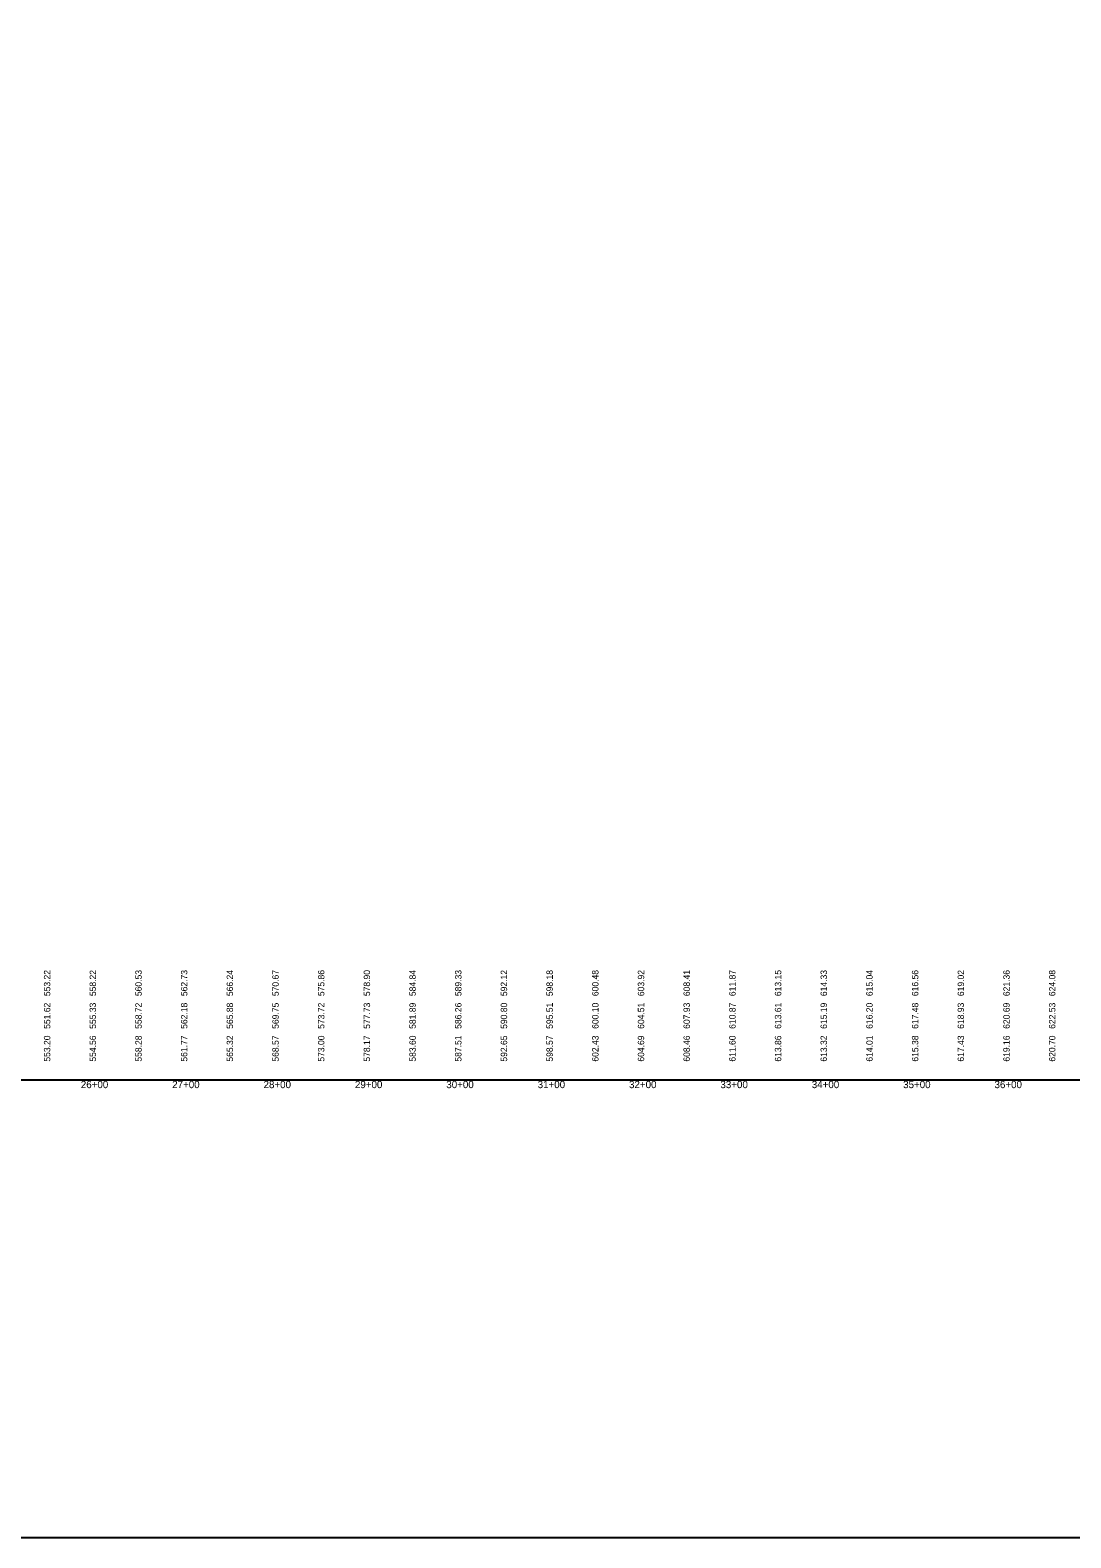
# Model space of a CAD drawing. Extents: x 1511486 to 1516886, y 901686 to 906985.
# Drawn here: x 1514602 to 1515741, y 903685 to 905335 of the extents above; entities that cross this region are included whole.
import ezdxf

# ---------------------------------------------------------------- set-up
doc = ezdxf.new("R2010")
doc.units = 0
for name, color, linetype in [('RD_DDB_StaTX', 7, 'Continuous'), ('RD_DDB_StripGrade', 7, 'Continuous'), ('RD_GPK_Profile_Cell', 7, 'Continuous'), ('RD_Sketch2', 7, 'Continuous'), ('RD_Sketch3', 7, 'Continuous')]:
    doc.layers.add(name, color=color, linetype=linetype)

msp = doc.modelspace()

# ---------------------------------------------------------------- linework, layer by layer
at = {"layer": 'RD_GPK_Profile_Cell'}
msp.add_line((1512074.7, 904186.4), (1516174.7, 904186.4), dxfattribs=at)
at = {"layer": 'RD_Sketch3'}
msp.add_lwpolyline([(1511486.2, 906985.3), (1516886.2, 906985.3), (1516886.2, 903685.3), (1511486.2, 903685.3)], close=True, dxfattribs=at)

# ---------------------------------------------------------------- texts
at = {"layer": 'RD_DDB_StaTX'}
for s, p in [('26+00', (1514657.1, 904177.4)), ('27+00', (1514757.1, 904177.4)), ('28+00', (1514857.1, 904177.4)), ('29+00', (1514957.1, 904177.4)), ('30+00', (1515057.1, 904177.4)), ('31+00', (1515157.1, 904177.4)), ('32+00', (1515257.1, 904177.4)), ('33+00', (1515357.1, 904177.4)), ('34+00', (1515457.1, 904177.4)), ('35+00', (1515557.1, 904177.4)), ('36+00', (1515657.1, 904177.4))]:
    msp.add_text(s, height=8, dxfattribs=at).set_placement(p)
at = {"layer": 'RD_DDB_StripGrade'}
for s, p in [('551.62', (1514623.7, 904242.3)), ('555.33', (1514673.7, 904242.3)), ('558.72', (1514723.7, 904242.3)), ('562.18', (1514773.7, 904242.3)), ('565.88', (1514823.7, 904242.3)), ('569.75', (1514873.7, 904242.3)), ('573.72', (1514923.7, 904242.3)), ('577.73', (1514973.7, 904242.3)), ('581.89', (1515023.7, 904242.3)), ('586.26', (1515073.7, 904242.3)), ('590.80', (1515123.7, 904242.3)), ('595.51', (1515173.7, 904242.3)), ('600.10', (1515223.7, 904242.3)), ('604.51', (1515273.7, 904242.3)), ('607.93', (1515323.7, 904242.3)), ('610.87', (1515373.7, 904242.3)), ('613.61', (1515423.7, 904242.3)), ('615.19', (1515473.7, 904242.3)), ('616.20', (1515523.7, 904242.3)), ('617.48', (1515573.7, 904242.3)), ('618.93', (1515623.7, 904242.3)), ('620.69', (1515673.7, 904242.3)), ('622.53', (1515723.7, 904242.3))]:
    msp.add_text(s, height=7, rotation=90, dxfattribs=at).set_placement(p)
at = {"layer": 'RD_Sketch2'}
for s, p in [('553.22', (1514623.7, 904278.1)), ('558.22', (1514673.7, 904278.1)), ('560.53', (1514723.7, 904278.1)), ('562.73', (1514773.7, 904278.1)), ('566.24', (1514823.7, 904278.1)), ('570.67', (1514873.7, 904278.1)), ('575.86', (1514923.7, 904278.1)), ('578.90', (1514973.7, 904278.1)), ('584.84', (1515023.7, 904278.1)), ('589.33', (1515073.7, 904278.1)), ('592.12', (1515123.7, 904278.1)), ('598.18', (1515173.7, 904278.1)), ('600.48', (1515223.7, 904278.1)), ('603.92', (1515273.7, 904278.1)), ('608.41', (1515323.7, 904278.1)), ('611.87', (1515373.7, 904278.1)), ('613.15', (1515423.7, 904278.1)), ('614.33', (1515473.7, 904278.1)), ('615.04', (1515523.7, 904278.1)), ('616.56', (1515573.7, 904278.1)), ('619.02', (1515623.7, 904278.1)), ('621.36', (1515673.7, 904278.1)), ('624.08', (1515723.7, 904278.1)), ('553.20', (1514623.7, 904206.4)), ('554.56', (1514673.7, 904206.4)), ('558.28', (1514723.7, 904206.4)), ('561.77', (1514773.7, 904206.4)), ('565.32', (1514823.7, 904206.4)), ('568.57', (1514873.7, 904206.4)), ('573.00', (1514923.7, 904206.4)), ('578.17', (1514973.7, 904206.4)), ('583.60', (1515023.7, 904206.4)), ('587.51', (1515073.7, 904206.4)), ('592.65', (1515123.7, 904206.4)), ('598.57', (1515173.7, 904206.4)), ('602.43', (1515223.7, 904206.4)), ('604.69', (1515273.7, 904206.4)), ('608.46', (1515323.7, 904206.4)), ('611.60', (1515373.7, 904206.4)), ('613.86', (1515423.7, 904206.4)), ('613.32', (1515473.7, 904206.4)), ('614.01', (1515523.7, 904206.4)), ('615.38', (1515573.7, 904206.4)), ('617.43', (1515623.7, 904206.4)), ('619.16', (1515673.7, 904206.4)), ('620.70', (1515723.7, 904206.4))]:
    msp.add_text(s, height=7, rotation=90, dxfattribs=at).set_placement(p)

doc.saveas('drawing.dxf')
